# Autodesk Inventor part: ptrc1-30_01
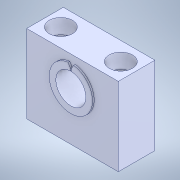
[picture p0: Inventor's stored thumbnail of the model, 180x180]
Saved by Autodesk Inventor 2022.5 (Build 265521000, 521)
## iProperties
Created: 2023-04
Part Number: ptrc1-30_01
Material: Generic
Document SubType Name: Modeling
Designer: ImaoCorp
Density: 1 g/cm^3
Appearance: Default
Author: ImaoCorp
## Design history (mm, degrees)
feature "ptrc1-30_01"
node "ソリッド1"
